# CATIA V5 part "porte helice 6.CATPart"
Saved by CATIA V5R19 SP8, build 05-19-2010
Part number: porte helice 6
Bounding box of the stored display mesh (mm): x -20 to 20, y -50 to 180, z -20 to 20
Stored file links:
  G:\EU_thinkMotion\CFAO_2010\MMS_groupe2\MMS_groupe2\A reprendre\splanchenault\Planchenault\porte helice 6.CATPart
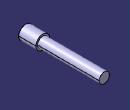
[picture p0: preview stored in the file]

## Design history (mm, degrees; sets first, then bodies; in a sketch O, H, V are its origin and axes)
Body1 (main body)
  Sketch1 on zx-plane, origin (0, 0, 0), H (-1, 0, 0), V (0, 0, 1)
    circle A1 centre (0, 0) radius 15
    radius A1 = 15
  Pad1: profile Sketch1, direction (0, 1, 0), length 180
  Sketch2 on start face of Pad1, origin (0, 0, 0), H (1, 0, 0), V (0, 0, 1)
    circle A1 centre (0, 0) radius 20
    radius A1 = 20
  Pad2: profile Sketch2, direction (0, -1, 0), length 50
